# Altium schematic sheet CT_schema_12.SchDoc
size 389 x 385 mm
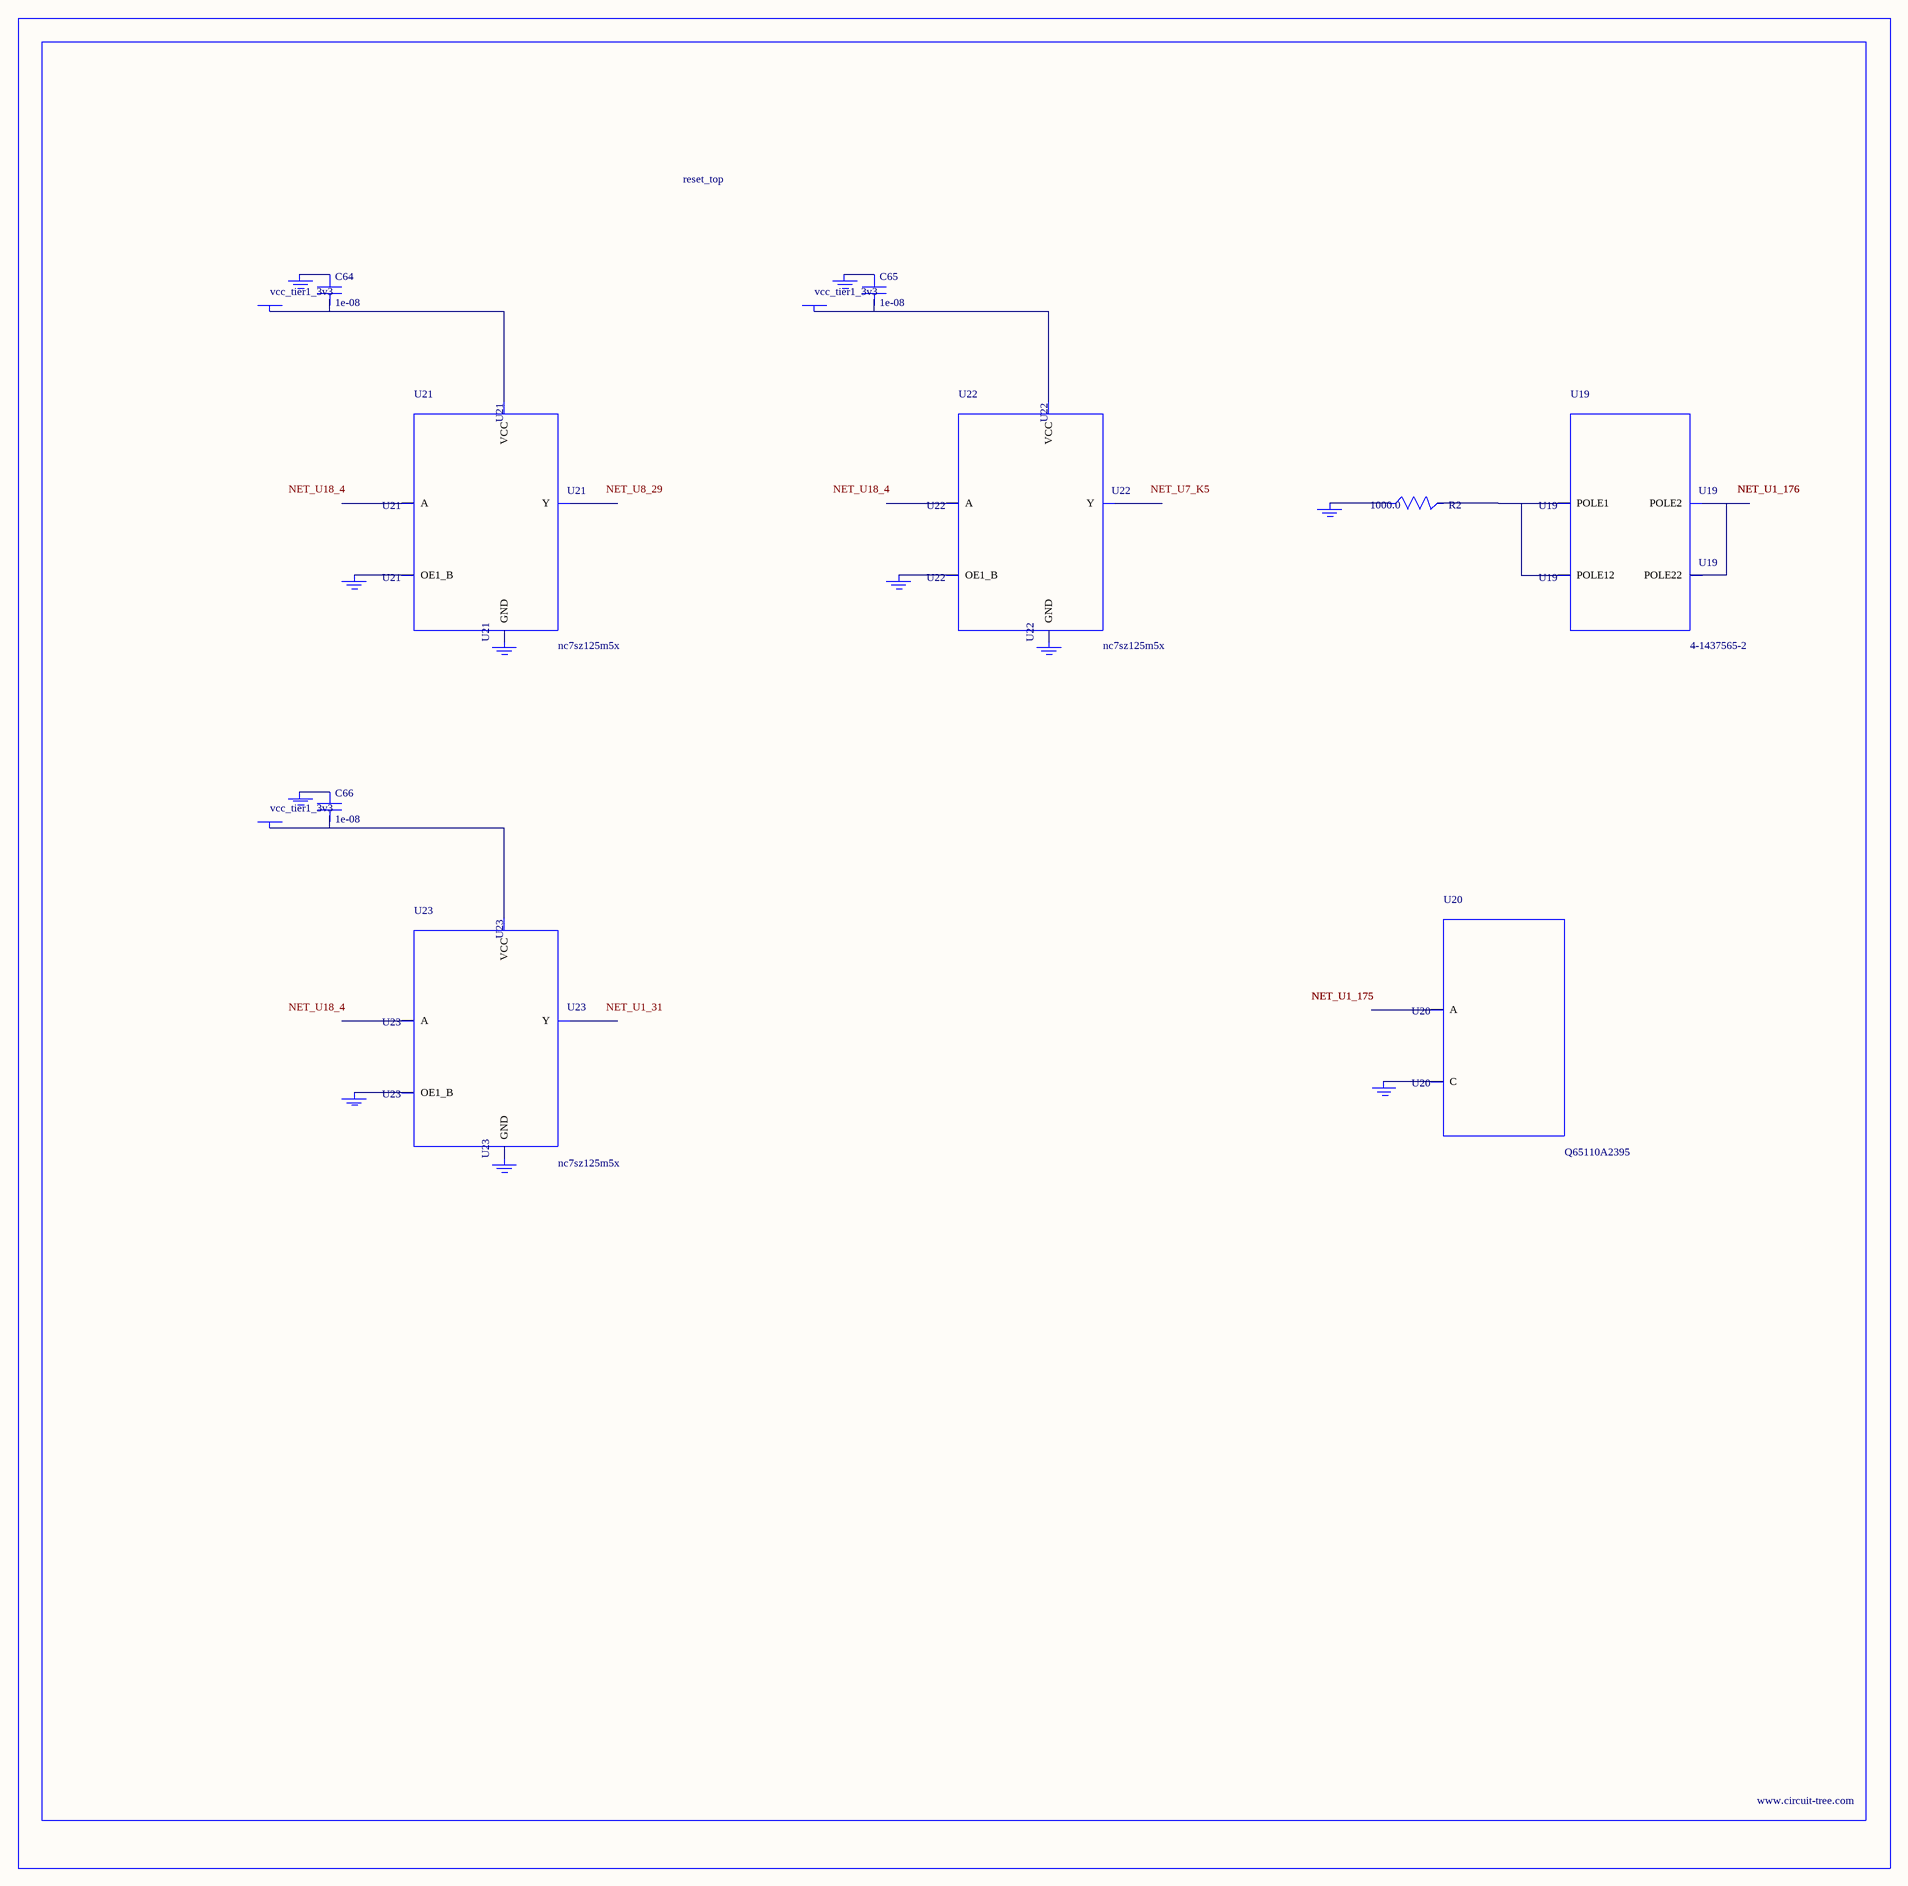
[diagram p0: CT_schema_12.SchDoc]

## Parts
BORDER11  (no value)
C64  1e-08  [C0402]
C65  1e-08  [C0402]
C66  1e-08  [C0402]
GND_INSTANCE_11_0  (no value)
GND_INSTANCE_11_1  (no value)
GND_INSTANCE_11_2  (no value)
GND_INSTANCE_11_3  (no value)
GND_INSTANCE_11_4  (no value)
GND_INSTANCE_11_5  (no value)
GND_INSTANCE_11_6  (no value)
GND_INSTANCE_11_7  (no value)
GND_INSTANCE_11_8  (no value)
GND_INSTANCE_11_9  (no value)
GND_INSTANCE_11_10  (no value)
POWER_INSTANCE_11_0  vcc_tier1_3v3
POWER_INSTANCE_11_1  vcc_tier1_3v3
POWER_INSTANCE_11_2  vcc_tier1_3v3
R2  1000.0  [R0603]
U19  4-1437565-2  [SW_4-1437565-2]
U20  Q65110A2395  [LGM67K-G1J2-24-Z]
U21  nc7sz125m5x  [NC7SZ125M5X]
U22  nc7sz125m5x  [NC7SZ125M5X]
U23  nc7sz125m5x  [NC7SZ125M5X]

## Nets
NetC64_1: C64.1 GND_INSTANCE_11_2.0(GND)
NetC64_2: C64.2 POWER_INSTANCE_11_0.0(PWR) U21.5(VCC)
NetC65_1: C65.1 GND_INSTANCE_11_5.0(GND)
NetC65_2: C65.2 POWER_INSTANCE_11_1.0(PWR) U22.5(VCC)
NetC66_1: C66.1 GND_INSTANCE_11_8.0(GND)
NetC66_2: C66.2 POWER_INSTANCE_11_2.0(PWR) U23.5(VCC)
NetGND_INSTANCE_11_0_0: GND_INSTANCE_11_0.0(GND) R2.1
NetGND_INSTANCE_11_1_0: GND_INSTANCE_11_1.0(GND) U20.C
NetGND_INSTANCE_11_3_0: GND_INSTANCE_11_3.0(GND) U21.1(OE1_B)
NetGND_INSTANCE_11_4_0: GND_INSTANCE_11_4.0(GND) U21.3(GND)
NetGND_INSTANCE_11_6_0: GND_INSTANCE_11_6.0(GND) U22.1(OE1_B)
NetGND_INSTANCE_11_7_0: GND_INSTANCE_11_7.0(GND) U22.3(GND)
NetGND_INSTANCE_11_9_0: GND_INSTANCE_11_9.0(GND) U23.1(OE1_B)
NetGND_INSTANCE_11_10_0: GND_INSTANCE_11_10.0(GND) U23.3(GND)
NetR2_2: R2.2 U19.1(POLE1) U19.2(POLE12)
NetU19_3: U19.3(POLE2) U19.4(POLE22)

Not connected (* = marked no-connect by the designer): U20 A; U21 2(A) 4(Y); U22 2(A) 4(Y); U23 2(A) 4(Y)

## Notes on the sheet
- Labels drawn without touching a wire or pin: NET_U1_31, NET_U7_K5, NET_U8_29, NET_U18_4

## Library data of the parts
BORDER11 = BORDER_PAGE11
C64-C66 = C0402C103K3RAC
GND_INSTANCE_11_0-GND_INSTANCE_11_10 = GND
POWER_INSTANCE_11_0-POWER_INSTANCE_11_2 = PWR
R2 = RC0603JR-071KL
